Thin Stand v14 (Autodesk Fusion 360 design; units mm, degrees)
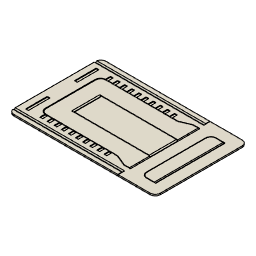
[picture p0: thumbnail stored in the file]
parameter "PhoneThickness" = 7
parameter "d60" = 1.5
parameter "d61" = 2
parameter "d62" = 0.75 (= "0.5 * d60")
sketch "Sketch1" plane through (0, 0, 0) normal (0, 1, 0) x axis (1, 0, 0)
  line L1 (43, 27) -> (-43, 27)
  line L2 (43, -27) -> (43, 27)
  line L3 (-43, -27) -> (43, -27)
  line L4 (-43, 27) -> (-43, -27)
  line L5 (43, -27) -> (-43, 27)
  line L6 (-43, -27) -> (43, 27)
  line L7 (-43, 0) -> (43, 0)
  line L8 (28.2, 20.4) -> (28.2, 0)
  line L9 (36.2, 20.4) -> (28.2, 20.4)
  line L10 (36.2, 0) -> (36.2, 20.4)
  line L11 (28.4, 20.2) -> (28.4, 0)
  line L12 (36, 20.2) -> (28.4, 20.2)
  line L13 (36, 0) -> (36, 20.2)
  line L14 (-24, 8) -> (21, 8)
  line L15 (-24, 0) -> (-24, 8)
  line L16 (21, 8) -> (21, 0)
  line L17 (21.2, 8.2) -> (21.2, 0)
  line L18 (-24.2, 8.2) -> (21, 8.2)
  line L19 (-24.2, 0) -> (-24.2, 8.2)
  line L20 (-33.5, 17.5) -> (-33.5, 0)
  line L21 (11.5, 17.5) -> (-33.5, 17.5)
  line L22 (21, 20.2) -> (21, 8.2)
  line L23 (18, 20.2) -> (21, 20.2)
  line L24 (11.5, 17.5) -> (18, 20.2)
  line L25 (21.2, 20.4) -> (21.2, 8.2)
  line L26 (17.9601, 20.4) -> (21.2, 20.4)
  line L27 (11.4601, 17.7) -> (17.9601, 20.4)
  line L28 (11.4601, 17.7) -> (-33.7, 17.7)
  line L29 (-33.7, 17.7) -> (-33.7, 0)
  line L30 (-33.5, -17.5) -> (-33.5, 0)
  line L31 (11.5, -17.5) -> (-33.5, -17.5)
  line L32 (18, -20.2) -> (21, -20.2)
  line L33 (21, -20.2) -> (21, -8.2)
  line L34 (21.2, -20.4) -> (21.2, -8.2)
  line L35 (21, -8) -> (21, 0)
  line L36 (21.2, -8.2) -> (21.2, 0)
  line L37 (-24, -8) -> (21, -8)
  line L38 (-24.2, -8.2) -> (21, -8.2)
  line L39 (-24.2, 0) -> (-24.2, -8.2)
  line L40 (-24, 0) -> (-24, -8)
  line L41 (28.2, -20.4) -> (28.2, 0)
  line L42 (28.4, -20.2) -> (28.4, 0)
  line L43 (17.9601, -20.4) -> (21.2, -20.4)
  line L44 (11.5, -17.5) -> (18, -20.2)
  line L45 (11.4601, -17.7) -> (17.9601, -20.4)
  line L46 (11.4601, -17.7) -> (-33.7, -17.7)
  line L47 (-33.7, -17.7) -> (-33.7, 0)
  line L48 (36.2, -20.4) -> (28.2, -20.4)
  line L49 (36, -20.2) -> (28.4, -20.2)
  line L50 (36, 0) -> (36, -20.2)
  line L51 (36.2, 0) -> (36.2, -20.4)
  line L52 (43, 24) -> (-43, 24)
  line L53 (43, 23.8) -> (-43, 23.8)
  line L54 (21.2, 27) -> (21.2, 24)
  line L55 (21, 27) -> (21, 24)
  line L56 (43, -23.8) -> (-43, -23.8)
  line L57 (43, -24) -> (-43, -24)
  line L58 (21, -27) -> (21, -24)
  line L59 (21.2, -27) -> (21.2, -24)
  line L60 (21.2, 23.8) -> (21.2, 24)
  line L61 (21.2, -23.8) -> (21.2, -24)
  line L62 (-33.9, 17.9) -> (-33.9, 0)
  line L63 (11.4202, 17.9) -> (-33.9, 17.9)
  line L64 (11.4202, 17.9) -> (17.9202, 20.6)
  line L65 (17.9202, 20.6) -> (21.4, 20.6)
  line L66 (21.4, 20.6) -> (21.4, 7.8)
  line L67 (-23.8, 7.8) -> (21.4, 7.8)
  line L68 (-23.8, 0) -> (-23.8, 7.8)
  line L69 (-33.9, 17.7) -> (-33.7, 17.7)
  line L70 (-33.9, -17.7) -> (-33.7, -17.7)
  line L71 (-33.9, -17.9) -> (-33.9, 0)
  line L72 (-23.323, 10.3151) -> (21, 10.3151)
  point P6 (0, 0)
  point P1 (0, 0)
  point P7 (43, 0)
  point P8 (-43, 0)
  point P9 (28.2, 0)
  point P12 (36.2, 0)
  point P19 (-24, 0)
  point P20 (21, 0)
  point P25 (-33.5, 0)
  point P30 (21.2, 8.2)
  point P36 (21.2, 8.2)
  point P21 (21.2, 0)
  point P24 (-24.2, 0)
  point P53 (28.2, 0)
  point P10 (28.2, 20.4)
  point P54 (28.2, -20.4)
  point P11 (36.2, 20.4)
  point P61 (36.2, -20.4)
  point P64 (36.2, 0)
  point P13 (28.4, 0)
  point P55 (28.4, 0)
  point P14 (28.4, 20.2)
  point P56 (28.4, -20.2)
  point P15 (36, 20.2)
  point P62 (36, -20.2)
  point P16 (36, 0)
  point P63 (36, 0)
  point P17 (21, 8)
  point P46 (21, -8)
  point P18 (-24, 8)
  point P49 (-24, -8)
  point P52 (-24, 0)
  point P45 (21, 0)
  point P47 (21.2, 0)
  point P22 (21, 8.2)
  point P42 (21, -8.2)
  point P23 (-24.2, 8.2)
  point P50 (-24.2, -8.2)
  point P51 (-24.2, 0)
  point P37 (-33.5, 0)
  point P26 (-33.5, 17.5)
  point P38 (-33.5, -17.5)
  point P27 (11.5, 17.5)
  point P39 (11.5, -17.5)
  point P28 (21, 20.2)
  point P40 (21, -20.2)
  point P29 (18, 20.2)
  point P41 (18, -20.2)
  point P43 (21.2, -8.2)
  point P31 (21.2, 20.4)
  point P44 (21.2, -20.4)
  point P32 (17.9601, 20.4)
  point P57 (17.9601, -20.4)
  point P33 (11.4601, 17.7)
  point P58 (11.4601, -17.7)
  point P34 (-33.7, 17.7)
  point P59 (-33.7, -17.7)
  point P35 (-33.7, 0)
  point P60 (-33.7, 0)
  point P48 (21.2, -8.2)
  point P65 (-43, 24)
  point P66 (43, 24)
  point P69 (21.2, 24)
  point P70 (21.2, 27)
  point P75 (-43, -24)
  point P76 (43, -24)
  point P67 (-43, 23.8)
  point P73 (-43, -23.8)
  point P68 (43, 23.8)
  point P74 (43, -23.8)
  point P79 (21.2, -24)
  point P80 (21.2, -27)
  point P71 (21, 24)
  point P77 (21, -24)
  point P72 (21, 27)
  point P78 (21, -27)
  point P81 (21.2, 23.8)
  point P82 (21.2, -24)
  point P83 (21.2, -23.8)
  point P92 (-33.9, 17.7)
  point P93 (-33.7, -17.7)
  point P84 (-33.9, 0)
  point P95 (-33.9, 0)
  point P85 (-33.9, 17.9)
  point P96 (-33.9, -17.9)
  point P94 (-33.9, -17.7)
  point P97 (21, 10.3151)
  point P3 (43, 27)
  point P4 (43, -27)
  point P2 (-43, 27)
  horizontal L1
  perpendicular L1 L2
  parallel L1 L3
  parallel L2 L4
  coincident L5 P6
  coincident L6 P6
  coincident P1 P6
  midpoint L2 P7
  midpoint L4 P8
  coincident L7 P9
  perpendicular L7 L8
  perpendicular L8 L9
  coincident L7 P12
  perpendicular L7 L10
  horizontal L14
  vertical L15
  vertical L16
  coincident L7 P19
  coincident L7 P20
  coincident L7 P25
  perpendicular L7 L20
  perpendicular L20 L21
  perpendicular L18 L22
  perpendicular L22 L23
  parallel L16 L17
  parallel L14 L18
  parallel L15 L19
  coincident P30 P36
  coincident L7 P21
  coincident L7 P24
  symmetric L7 P9 P53
  symmetric L7 P10 P54
  symmetric L7 P11 P61
  symmetric L7 P12 P64
  symmetric L7 P13 P55
  symmetric L7 P14 P56
  symmetric L7 P15 P62
  symmetric L7 P16 P63
  symmetric L7 P17 P46
  symmetric L7 P18 P49
  symmetric L7 P19 P52
  symmetric L7 P20 P45
  symmetric L7 P21 P47
  symmetric L7 P22 P42
  symmetric L7 P23 P50
  symmetric L7 P24 P51
  symmetric L7 P25 P37
  symmetric L7 P26 P38
  symmetric L7 P27 P39
  symmetric L7 P28 P40
  symmetric L7 P29 P41
  symmetric L7 P30 P43
  symmetric L7 P31 P44
  symmetric L7 P32 P57
  symmetric L7 P33 P58
  symmetric L7 P34 P59
  symmetric L7 P35 P60
  symmetric L7 P36 P48
  coincident L4 P65
  coincident L2 P66
  perpendicular L2 L52
  coincident L52 P69
  coincident L1 P70
  perpendicular L1 L54
  symmetric L7 P65 P75
  symmetric L7 P66 P76
  symmetric L7 P67 P73
  symmetric L7 P68 P74
  symmetric L7 P69 P79
  symmetric L7 P70 P80
  symmetric L7 P71 P77
  symmetric L7 P72 P78
  coincident L53 P81
  perpendicular L53 L60
  symmetric L7 P69 P82
  symmetric L7 P81 P83
  coincident L62 P92
  perpendicular L62 L69
  symmetric L7 P34 P93
  symmetric L7 P84 P95
  symmetric L7 P85 P96
  symmetric L7 P92 P94
  coincident L22 P97
  perpendicular L19 L72
  dimension "d1" distance P3 P4 = 54
  dimension "d2" distance P2 P3 = 86
  dimension "d3" distance P10 P11 = 8
  dimension "d4" distance P9 P10 = 20.4
  dimension "d6" = 0.2
  dimension "d7" distance P17 P18 = 45
  dimension "d8" distance L2 L16 = 22
  dimension "d9" distance P17 P20 = 8
  dimension "d11" distance P26 P27 = 45
  dimension "d12" distance P22 P28 = 12
  dimension "d13" distance P28 P29 = 3
  dimension "d14" distance P25 P26 = 17.5
  dimension "d15" distance L15 L20 = 9.5
  dimension "d16" = 0.2
  dimension "d17" distance L14 L18 = 0.2
  dimension "d18" distance L20 L22 = 54.5
  dimension "d19" distance L15 L19 = 0.2
  dimension "d22" distance L8 L17 = 7 (= "PhoneThickness")
  dimension "d49" = 0.2
  dimension "d50" distance L1 L52 = 3
  dimension "d51" = -0.2
  dimension "d52" distance L8 L54 = 7 (= "PhoneThickness")
  dimension "d55" = -0.4
extrude "Extrude1" new body sketch "Sketch1" profile of L1 L2 L3 L4 L8 L9 L10 L11 L13 L12 L14 L15 L16 L17 L18 L19 L20 L21 L22 L23 L24 L27 L25 L26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 along normal blind 0.8
sketch "Sketch2" plane through (0, 0, 0) normal (0, 1, 0) x axis (1, 0, 0)
  line L1 (28.4, -20.2) -> (28.4, 20.2)
  line L2 (36, -20.2) -> (28.4, -20.2)
  line L3 (36, 20.2) -> (36, -20.2)
  line L4 (28.4, 20.2) -> (36, 20.2)
  line L5 (-43, -23.8) -> (-43, 23.8)
  line L6 (43, -27) -> (21.2, -27)
  line L7 (43, 27) -> (43, -27)
  line L8 (21.2, 27) -> (43, 27)
  line L9 (28.2, 20.4) -> (28.2, -20.4)
  line L10 (36.2, 20.4) -> (28.2, 20.4)
  line L11 (36.2, -20.4) -> (36.2, 20.4)
  line L12 (28.2, -20.4) -> (36.2, -20.4)
  line L13 (11.4601, 17.7) -> (-33.9, 17.7)
  line L14 (17.9601, 20.4) -> (11.4601, 17.7)
  line L15 (21.2, 20.4) -> (17.9601, 20.4)
  line L16 (21.2, -20.4) -> (21.2, 20.4)
  line L17 (17.9601, -20.4) -> (21.2, -20.4)
  line L18 (11.4601, -17.7) -> (17.9601, -20.4)
  line L19 (-33.9, -17.7) -> (11.4601, -17.7)
  line L20 (21, 20.2) -> (21, 8.2)
  line L21 (-24.2, -8.2) -> (21, -8.2)
  line L22 (-24.2, 8.2) -> (-24.2, -8.2)
  line L23 (21, 8.2) -> (-24.2, 8.2)
  line L24 (21, 20.2) -> (21, 8.2)
  line L25 (18, 20.2) -> (21, 20.2)
  line L26 (11.5, 17.5) -> (18, 20.2)
  line L27 (-33.5, 17.5) -> (11.5, 17.5)
  line L28 (-33.5, -17.5) -> (-33.5, 17.5)
  line L29 (11.5, -17.5) -> (-33.5, -17.5)
  line L30 (18, -20.2) -> (11.5, -17.5)
  line L31 (21, -20.2) -> (18, -20.2)
  line L32 (21, -8.2) -> (21, -20.2)
  line L33 (21, 8) -> (21, -8)
  line L34 (-24, 8) -> (21, 8)
  line L35 (-24, -8) -> (-24, 8)
  line L36 (21, -8) -> (-24, -8)
  line L37 (36.2, 20.2) -> (36, 20.2)
  line L38 (36.2, -20.2) -> (36, -20.2)
  line L39 (21.2, -8) -> (21, -8)
  line L40 (21.2, 8) -> (21, 8)
  line L41 (-24.2, 8) -> (-24, 8)
  line L42 (-24.2, -8) -> (-24, -8)
  line L43 (21.2, 23.8) -> (21.2, 27)
  line L44 (-43, 23.8) -> (21.2, 23.8)
  line L45 (21.2, -23.8) -> (-43, -23.8)
  line L46 (21.2, -27) -> (21.2, -23.8)
  line L47 (21, -24) -> (-43, -24)
  line L48 (21, -27) -> (21, -24)
  line L49 (-43, -27) -> (21, -27)
  line L50 (21, 27) -> (-43, 27)
  line L51 (21, 24) -> (21, 27)
  line L52 (-43, 24) -> (21, 24)
  line L53 (21, -23.8) -> (21, -24)
  line L54 (-43, -24) -> (-43, -23.8)
  line L55 (-43, 23.8) -> (-43, 24)
  line L56 (-43, -24) -> (-43, -27)
  line L57 (-43, 27) -> (-43, 24)
  line L58 (21, 23.8) -> (21, 24)
  line L59 (-33.9, 17.7) -> (-33.9, -17.7)
  point P5 (36, 20.2)
  point P44 (36, 20.2)
  point P45 (36.2, 20.2)
  point P4 (36, -20.2)
  point P46 (36, -20.2)
  point P47 (36.2, -20.2)
  point P40 (21, -8)
  point P48 (21, -8)
  point P49 (21.2, -8)
  point P41 (21, 8)
  point P50 (21, 8)
  point P51 (21.2, 8)
  point P42 (-24, 8)
  point P52 (-24, 8)
  point P53 (-24.2, 8)
  point P43 (-24, -8)
  point P54 (-24, -8)
  point P55 (-24.2, -8)
  point P60 (21, -24)
  point P66 (21, -24)
  point P67 (21, -23.8)
  point P8 (-43, -23.8)
  point P68 (-43, -23.8)
  point P58 (-43, -24)
  point P69 (-43, -24)
  point P63 (-43, 24)
  point P70 (-43, 24)
  point P7 (-43, 23.8)
  point P71 (-43, 23.8)
  point P65 (21, 24)
  point P72 (21, 24)
  point P73 (21, 23.8)
  coincident P5 P44
  coincident L11 P45
  perpendicular L11 L37
  coincident P4 P46
  coincident L11 P47
  perpendicular L11 L38
  coincident P40 P48
  coincident L16 P49
  perpendicular L16 L39
  coincident P41 P50
  coincident L16 P51
  perpendicular L16 L40
  coincident P42 P52
  coincident L22 P53
  perpendicular L22 L41
  coincident P43 P54
  coincident L22 P55
  perpendicular L22 L42
  coincident P60 P66
  coincident L45 P67
  perpendicular L45 L53
  coincident P8 P68
  coincident P58 P69
  coincident P63 P70
  coincident P7 P71
  coincident P65 P72
  coincident L44 P73
  perpendicular L44 L58
extrude "Extrude2" add sketch "Sketch2" profile of L3 L11 L16 L22 L33 L35 L37 L38 L39 L40 L41 L42 L44 L45 L47 L52 L53 L54 L55 L58 along normal blind 0.2
chamfer "Chamfer1" distance 0.6
fillet "Fillet2" radius 3
sketch "Sketch3" plane through (0, 0.8, 0) normal (0, 1, 0) x axis (-1, 0, 0)
  line L1 (30.9, 17.7) -> (-10.8618, 17.7)
  line L2 (-10.8618, -17.7) -> (30.9, -17.7)
  line L3 (-17.9601, -20.4) -> (-12.0126, -17.9295)
  line L4 (-21.8, -20.4) -> (-17.9601, -20.4)
  line L5 (-21.8, 20.4) -> (-21.8, -20.4)
  line L6 (-17.9601, 20.4) -> (-21.8, 20.4)
  line L7 (-12.0126, 17.9295) -> (-17.9601, 20.4)
  line L8 (-31.2, 20.4) -> (-36.2, 20.4)
  line L9 (-28.2, -17.4) -> (-28.2, 17.4)
  line L10 (-36.2, -20.4) -> (-31.2, -20.4)
  line L11 (43, 23.2) -> (43, -23.2)
  line L12 (-43, 27) -> (-21.2, 27)
  line L13 (-43, -27) -> (-43, 27)
  line L14 (-21.2, -27) -> (-43, -27)
  line L15 (-7.8618, -17.7) -> (-10.8618, -17.7)
  line L16 (-7.8618, -20.7) -> (-7.8618, -17.7)
  line L17 (-6.6618, -20.7) -> (-7.8618, -20.7)
  line L18 (-6.6618, -17.7) -> (-6.6618, -20.7)
  line L19 (-6.6618, -8) -> (-6.6618, -17.7)
  line L20 (-7.8618, -8) -> (-6.6618, -8)
  line L21 (-7.8618, -17.7) -> (-7.8618, -8)
  line L22 (23.4, -8) -> (-20.4, -8)
  line L23 (-2.48, -17.7) -> (-2.48, -20.7)
  line L24 (-2.48, -8) -> (-2.48, -17.7)
  line L25 (-3.68, -17.7) -> (-3.68, -8)
  line L26 (-3.68, -20.7) -> (-3.68, -17.7)
  line L27 (-2.48, -20.7) -> (-3.68, -20.7)
  line L28 (-3.68, -8) -> (-2.48, -8)
  line L29 (-3.68, -17.7) -> (-6.68, -17.7)
  line L30 (1.7018, -17.7) -> (1.7018, -20.7)
  line L31 (1.7018, -8) -> (1.7018, -17.7)
  line L32 (0.5018, -17.7) -> (0.5018, -8)
  line L33 (0.5018, -20.7) -> (0.5018, -17.7)
  line L34 (1.7018, -20.7) -> (0.5018, -20.7)
  line L35 (0.5018, -8) -> (1.7018, -8)
  line L36 (0.5018, -17.7) -> (-2.4982, -17.7)
  line L37 (5.8836, -17.7) -> (5.8836, -20.7)
  line L38 (5.8836, -8) -> (5.8836, -17.7)
  line L39 (4.6836, -17.7) -> (4.6836, -8)
  line L40 (4.6836, -20.7) -> (4.6836, -17.7)
  line L41 (5.8836, -20.7) -> (4.6836, -20.7)
  line L42 (4.6836, -8) -> (5.8836, -8)
  line L43 (4.6836, -17.7) -> (1.6836, -17.7)
  line L44 (10.0655, -17.7) -> (10.0655, -20.7)
  line L45 (10.0655, -8) -> (10.0655, -17.7)
  line L46 (8.8655, -17.7) -> (8.8655, -8)
  line L47 (8.8655, -20.7) -> (8.8655, -17.7)
  line L48 (10.0655, -20.7) -> (8.8655, -20.7)
  line L49 (8.8655, -8) -> (10.0655, -8)
  line L50 (8.8655, -17.7) -> (5.8655, -17.7)
  line L51 (14.2473, -17.7) -> (14.2473, -20.7)
  line L52 (14.2473, -8) -> (14.2473, -17.7)
  line L53 (13.0473, -17.7) -> (13.0473, -8)
  line L54 (13.0473, -20.7) -> (13.0473, -17.7)
  line L55 (14.2473, -20.7) -> (13.0473, -20.7)
  line L56 (13.0473, -8) -> (14.2473, -8)
  line L57 (13.0473, -17.7) -> (10.0473, -17.7)
  line L58 (18.4291, -17.7) -> (18.4291, -20.7)
  line L59 (18.4291, -8) -> (18.4291, -17.7)
  line L60 (17.2291, -17.7) -> (17.2291, -8)
  line L61 (17.2291, -20.7) -> (17.2291, -17.7)
  line L62 (18.4291, -20.7) -> (17.2291, -20.7)
  line L63 (17.2291, -8) -> (18.4291, -8)
  line L64 (17.2291, -17.7) -> (14.2291, -17.7)
  line L65 (22.6109, -17.7) -> (22.6109, -20.7)
  line L66 (22.6109, -8) -> (22.6109, -17.7)
  line L67 (21.4109, -17.7) -> (21.4109, -8)
  line L68 (21.4109, -20.7) -> (21.4109, -17.7)
  line L69 (22.6109, -20.7) -> (21.4109, -20.7)
  line L70 (21.4109, -8) -> (22.6109, -8)
  line L71 (21.4109, -17.7) -> (18.4109, -17.7)
  line L72 (26.7927, -17.7) -> (26.7927, -20.7)
  line L73 (26.7927, -8) -> (26.7927, -17.7)
  line L74 (25.5927, -17.7) -> (25.5927, -8)
  line L75 (25.5927, -20.7) -> (25.5927, -17.7)
  line L76 (26.7927, -20.7) -> (25.5927, -20.7)
  line L77 (25.5927, -8) -> (26.7927, -8)
  line L78 (25.5927, -17.7) -> (22.5927, -17.7)
  line L79 (30.9745, -17.7) -> (30.9745, -20.7)
  line L80 (30.9745, -8) -> (30.9745, -17.7)
  line L81 (29.7745, -17.7) -> (29.7745, -8)
  line L82 (29.7745, -20.7) -> (29.7745, -17.7)
  line L83 (30.9745, -20.7) -> (29.7745, -20.7)
  line L84 (29.7745, -8) -> (30.9745, -8)
  line L85 (29.7745, -17.7) -> (26.7745, -17.7)
  line L86 (35.1564, -17.7) -> (35.1564, -20.7)
  line L87 (35.1564, -8) -> (35.1564, -17.7)
  line L88 (33.9564, -17.7) -> (33.9564, -8)
  line L89 (33.9564, -20.7) -> (33.9564, -17.7)
  line L90 (35.1564, -20.7) -> (33.9564, -20.7)
  line L91 (33.9564, -8) -> (35.1564, -8)
  line L92 (33.9564, -17.7) -> (30.9564, -17.7)
  line L93 (39.3382, -17.7) -> (39.3382, -20.7)
  line L94 (39.3382, -8) -> (39.3382, -17.7)
  line L95 (38.1382, -17.7) -> (38.1382, -8)
  line L96 (38.1382, -20.7) -> (38.1382, -17.7)
  line L97 (39.3382, -20.7) -> (38.1382, -20.7)
  line L98 (38.1382, -8) -> (39.3382, -8)
  line L99 (38.1382, -17.7) -> (35.1382, -17.7)
  line L100 (10, 0) -> (0, 0)
  line L101 (38.1382, 8) -> (39.3382, 8)
  line L102 (21.4109, 20.7) -> (21.4109, 17.7)
  line L103 (25.5927, 17.7) -> (25.5927, 8)
  line L104 (29.7745, 8) -> (30.9745, 8)
  line L105 (17.2291, 17.7) -> (17.2291, 8)
  line L106 (1.7018, 20.7) -> (0.5018, 20.7)
  line L107 (0.5018, 20.7) -> (0.5018, 17.7)
  line L108 (-7.8618, 17.7) -> (-7.8618, 8)
  line L109 (22.6109, 17.7) -> (22.6109, 20.7)
  line L110 (17.2291, 17.7) -> (14.2291, 17.7)
  line L111 (25.5927, 20.7) -> (25.5927, 17.7)
  line L112 (-3.68, 17.7) -> (-6.68, 17.7)
  line L113 (33.9564, 20.7) -> (33.9564, 17.7)
  line L114 (-7.8618, 8) -> (-6.6618, 8)
  line L115 (35.1564, 20.7) -> (33.9564, 20.7)
  line L116 (13.0473, 8) -> (14.2473, 8)
  line L117 (17.2291, 20.7) -> (17.2291, 17.7)
  line L118 (22.6109, 20.7) -> (21.4109, 20.7)
  line L119 (25.5927, 17.7) -> (22.5927, 17.7)
  line L120 (39.3382, 8) -> (39.3382, 17.7)
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  point P7 (-10.8618, -17.7)
  point P30 (-10.8618, -17.7)
  point P34 (-6.6618, -17.7)
  point P36 (-7.8618, -8)
  point P1 (0, 0)
  point P116 (0, 0)
  point P6 (33.9, -14.7)
  point P155 (33.9, 14.7)
  point P142 (-10.8618, 17.7)
  point P8 (-12.0126, -17.9295)
  point P132 (-12.0126, 17.9295)
  point P10 (-17.9601, -20.4)
  point P207 (-17.9601, 20.4)
  point P11 (-21.8, -20.4)
  point P197 (-21.8, 20.4)
  point P22 (-21.2, -27)
  point P124 (-21.2, 27)
  point P23 (43, -23.2)
  point P183 (43, 23.2)
  point P202 (-10.8618, 17.7)
  point P31 (-7.8618, -17.7)
  point P156 (-7.8618, 17.7)
  point P32 (-7.8618, -20.7)
  point P150 (-7.8618, 20.7)
  point P33 (-6.6618, -20.7)
  point P158 (-6.6618, 20.7)
  point P210 (-6.6618, 17.7)
  point P35 (-6.6618, -8)
  point P120 (-6.6618, 8)
  point P187 (-7.8618, 8)
  point P37 (-20.4, -8)
  point P143 (-20.4, 8)
  point P38 (23.4, -8)
  point P118 (23.4, 8)
  point P39 (-2.48, -20.7)
  point P157 (-2.48, 20.7)
  point P40 (-2.48, -17.7)
  point P149 (-2.48, 17.7)
  point P41 (-2.48, -8)
  point P127 (-2.48, 8)
  point P42 (-3.68, -8)
  point P134 (-3.68, 8)
  point P43 (-3.68, -17.7)
  point P172 (-3.68, 17.7)
  point P44 (-3.68, -20.7)
  point P160 (-3.68, 20.7)
  point P45 (-6.68, -17.7)
  point P206 (-6.68, 17.7)
  point P46 (1.7018, -20.7)
  point P171 (1.7018, 20.7)
  point P47 (1.7018, -17.7)
  point P190 (1.7018, 17.7)
  point P48 (1.7018, -8)
  point P137 (1.7018, 8)
  point P49 (0.5018, -8)
  point P119 (0.5018, 8)
  point P50 (0.5018, -17.7)
  point P195 (0.5018, 17.7)
  point P51 (0.5018, -20.7)
  point P213 (0.5018, 20.7)
  point P52 (-2.4982, -17.7)
  point P200 (-2.4982, 17.7)
  point P53 (5.8836, -20.7)
  point P193 (5.8836, 20.7)
  point P54 (5.8836, -17.7)
  point P198 (5.8836, 17.7)
  point P55 (5.8836, -8)
  point P159 (5.8836, 8)
  point P56 (4.6836, -8)
  point P135 (4.6836, 8)
  point P57 (4.6836, -17.7)
  point P162 (4.6836, 17.7)
  point P58 (4.6836, -20.7)
  point P165 (4.6836, 20.7)
  point P59 (1.6836, -17.7)
  point P211 (1.6836, 17.7)
  point P60 (10.0655, -20.7)
  point P170 (10.0655, 20.7)
  point P61 (10.0655, -17.7)
  point P145 (10.0655, 17.7)
  point P62 (10.0655, -8)
  point P126 (10.0655, 8)
  point P63 (8.8655, -8)
  point P136 (8.8655, 8)
  point P64 (8.8655, -17.7)
  point P147 (8.8655, 17.7)
  point P65 (8.8655, -20.7)
  point P141 (8.8655, 20.7)
  point P66 (5.8655, -17.7)
  point P192 (5.8655, 17.7)
  point P67 (14.2473, -20.7)
  point P125 (14.2473, 20.7)
  point P68 (14.2473, -17.7)
  point P179 (14.2473, 17.7)
  point P69 (14.2473, -8)
  point P208 (14.2473, 8)
  point P70 (13.0473, -8)
  point P201 (13.0473, 8)
  point P71 (13.0473, -17.7)
  point P177 (13.0473, 17.7)
  point P72 (13.0473, -20.7)
  point P184 (13.0473, 20.7)
  point P73 (10.0473, -17.7)
  point P196 (10.0473, 17.7)
  point P74 (18.4291, -20.7)
  point P175 (18.4291, 20.7)
  point P75 (18.4291, -17.7)
  point P122 (18.4291, 17.7)
  point P76 (18.4291, -8)
  point P191 (18.4291, 8)
  point P77 (17.2291, -8)
  point P194 (17.2291, 8)
  point P78 (17.2291, -17.7)
  point P138 (17.2291, 17.7)
  point P79 (17.2291, -20.7)
  point P151 (17.2291, 20.7)
  point P80 (14.2291, -17.7)
  point P130 (14.2291, 17.7)
  point P81 (22.6109, -20.7)
  point P169 (22.6109, 20.7)
  point P82 (22.6109, -17.7)
  point P188 (22.6109, 17.7)
  point P83 (22.6109, -8)
  point P204 (22.6109, 8)
  point P84 (21.4109, -8)
  point P163 (21.4109, 8)
  point P85 (21.4109, -17.7)
  point P214 (21.4109, 17.7)
  point P86 (21.4109, -20.7)
  point P209 (21.4109, 20.7)
  point P87 (18.4109, -17.7)
  point P129 (18.4109, 17.7)
  point P88 (26.7927, -20.7)
  point P174 (26.7927, 20.7)
  point P89 (26.7927, -17.7)
  point P176 (26.7927, 17.7)
  point P90 (26.7927, -8)
  point P161 (26.7927, 8)
  point P91 (25.5927, -8)
  point P167 (25.5927, 8)
  point P92 (25.5927, -17.7)
  point P185 (25.5927, 17.7)
  point P93 (25.5927, -20.7)
  point P173 (25.5927, 20.7)
  point P94 (22.5927, -17.7)
  point P144 (22.5927, 17.7)
  point P95 (30.9745, -20.7)
  point P181 (30.9745, 20.7)
  point P96 (30.9745, -17.7)
  point P182 (30.9745, 17.7)
  point P97 (30.9745, -8)
  point P164 (30.9745, 8)
  point P98 (29.7745, -8)
  point P168 (29.7745, 8)
  point P99 (29.7745, -17.7)
  point P178 (29.7745, 17.7)
  point P100 (29.7745, -20.7)
  point P186 (29.7745, 20.7)
  point P101 (26.7745, -17.7)
  point P128 (26.7745, 17.7)
  point P102 (35.1564, -20.7)
  point P123 (35.1564, 20.7)
  point P103 (35.1564, -17.7)
  point P121 (35.1564, 17.7)
  point P104 (35.1564, -8)
  point P203 (35.1564, 8)
  point P105 (33.9564, -8)
  point P189 (33.9564, 8)
  point P106 (33.9564, -17.7)
  point P139 (33.9564, 17.7)
  point P107 (33.9564, -20.7)
  point P148 (33.9564, 20.7)
  point P108 (30.9564, -17.7)
  point P133 (30.9564, 17.7)
  point P109 (39.3382, -20.7)
  point P146 (39.3382, 20.7)
  point P110 (39.3382, -17.7)
  point P153 (39.3382, 17.7)
  point P111 (39.3382, -8)
  point P199 (39.3382, 8)
  point P112 (38.1382, -8)
  point P212 (38.1382, 8)
  point P113 (38.1382, -17.7)
  point P154 (38.1382, 17.7)
  point P114 (38.1382, -20.7)
  point P166 (38.1382, 20.7)
  point P115 (35.1382, -17.7)
  point P205 (35.1382, 17.7)
  coincident P7 P30
  parallel L2 L15
  perpendicular L15 L16
  perpendicular L16 L17
  coincident L2 P34
  perpendicular L2 L18
  perpendicular L2 L19
  perpendicular L19 L20
  perpendicular L15 L21
  coincident P36 L22
  coincident P1 P116
  perpendicular L9 L100
  symmetric P6 L100 P155
  symmetric P7 L100 P142
  symmetric P8 L100 P132
  symmetric P10 L100 P207
  symmetric P11 L100 P197
  symmetric P22 L100 P124
  symmetric P23 L100 P183
  symmetric P30 L100 P202
  symmetric P31 L100 P156
  symmetric P32 L100 P150
  symmetric P33 L100 P158
  symmetric P34 L100 P210
  symmetric P35 L100 P120
  symmetric P36 L100 P187
  symmetric P37 L100 P143
  symmetric P38 L100 P118
  symmetric P39 L100 P157
  symmetric P40 L100 P149
  symmetric P41 L100 P127
  symmetric P42 L100 P134
  symmetric P43 L100 P172
  symmetric P44 L100 P160
  symmetric P45 L100 P206
  symmetric P46 L100 P171
  symmetric P47 L100 P190
  symmetric P48 L100 P137
  symmetric P49 L100 P119
  symmetric P50 L100 P195
  symmetric P51 L100 P213
  symmetric P52 L100 P200
  symmetric P53 L100 P193
  symmetric P54 L100 P198
  symmetric P55 L100 P159
  symmetric P56 L100 P135
  symmetric P57 L100 P162
  symmetric P58 L100 P165
  symmetric P59 L100 P211
  symmetric P60 L100 P170
  symmetric P61 L100 P145
  symmetric P62 L100 P126
  symmetric P63 L100 P136
  symmetric P64 L100 P147
  symmetric P65 L100 P141
  symmetric P66 L100 P192
  symmetric P67 L100 P125
  symmetric P68 L100 P179
  symmetric P69 L100 P208
  symmetric P70 L100 P201
  symmetric P71 L100 P177
  symmetric P72 L100 P184
  symmetric P73 L100 P196
  symmetric P74 L100 P175
  symmetric P75 L100 P122
  symmetric P76 L100 P191
  symmetric P77 L100 P194
  symmetric P78 L100 P138
  symmetric P79 L100 P151
  symmetric P80 L100 P130
  symmetric P81 L100 P169
  symmetric P82 L100 P188
  symmetric P83 L100 P204
  symmetric P84 L100 P163
  symmetric P85 L100 P214
  symmetric P86 L100 P209
  symmetric P87 L100 P129
  symmetric P88 L100 P174
  symmetric P89 L100 P176
  symmetric P90 L100 P161
  symmetric P91 L100 P167
  symmetric P92 L100 P185
  symmetric P93 L100 P173
  symmetric P94 L100 P144
  symmetric P95 L100 P181
  symmetric P96 L100 P182
  symmetric P97 L100 P164
  symmetric P98 L100 P168
  symmetric P99 L100 P178
  symmetric P100 L100 P186
  symmetric P101 L100 P128
  symmetric P102 L100 P123
  symmetric P103 L100 P121
  symmetric P104 L100 P203
  symmetric P105 L100 P189
  symmetric P106 L100 P139
  symmetric P107 L100 P148
  symmetric P108 L100 P133
  symmetric P109 L100 P146
  symmetric P110 L100 P153
  symmetric P111 L100 P199
  symmetric P112 L100 P212
  symmetric P113 L100 P154
  symmetric P114 L100 P166
  symmetric P115 L100 P205
  dimension "d30" distance P30 P31 = 3
  dimension "d31" distance P31 P32 = 3
  dimension "d32" distance P32 P33 = 1.2
  dimension "d35" R-Pattern1-uDistance = 46
  dimension "d36" R-Pattern1-vDistance = 0
extrude "Extrude3" cut sketch "Sketch3" against normal blind 0.4
sketch "Sketch4" plane through (0, 0, 0) normal (0, -1, 0) x axis (1, 0, 0)
  line L1 (17.9601, 20.4) -> (12.0126, 17.9295)
  line L2 (21.2, 20.4) -> (17.9601, 20.4)
  line L3 (21.2, 8) -> (21.2, 20.4)
  line L4 (-24.2, 8) -> (21.2, 8)
  line L5 (-24.2, 8.2) -> (-24.2, 8)
  line L6 (21, 8.2) -> (-24.2, 8.2)
  line L7 (21, 20.2) -> (21, 8.2)
  line L8 (18, 20.2) -> (21, 20.2)
  line L9 (12.0525, 17.7295) -> (18, 20.2)
  line L10 (-30.5, 17.5) -> (10.9017, 17.5)
  line L11 (-33.5, -14.5) -> (-33.5, 14.5)
  line L12 (10.9017, -17.5) -> (-30.5, -17.5)
  line L13 (18, -20.2) -> (12.0525, -17.7295)
  line L14 (21, -20.2) -> (18, -20.2)
  line L15 (21, -8.2) -> (21, -20.2)
  line L16 (-24.2, -8.2) -> (21, -8.2)
  line L17 (-24.2, -8) -> (-24.2, -8.2)
  line L18 (21.2, -8) -> (-24.2, -8)
  line L19 (21.2, -20.4) -> (21.2, -8)
  line L20 (17.9601, -20.4) -> (21.2, -20.4)
  line L21 (12.0126, -17.9295) -> (17.9601, -20.4)
  line L22 (-30.9, -17.7) -> (10.8618, -17.7)
  line L23 (10.8618, 17.7) -> (-30.9, 17.7)
  line L24 (43, -27) -> (21.2, -27)
  line L25 (43, 27) -> (43, -27)
  line L26 (21.2, 27) -> (43, 27)
  line L27 (-43, 24) -> (-43, 27)
  line L28 (36.2, -20.2) -> (31.4, -20.2)
  line L29 (36.2, -20.4) -> (36.2, -20.2)
  line L30 (31.2, -20.4) -> (36.2, -20.4)
  line L31 (28.2, 17.4) -> (28.2, -17.4)
  line L32 (36.2, 20.4) -> (31.2, 20.4)
  line L33 (36.2, 20.2) -> (36.2, 20.4)
  line L34 (31.4, 20.2) -> (36.2, 20.2)
  line L35 (28.4, -17.2) -> (28.4, 17.2)
  line L36 (-33.5, 0) -> (-33.9, 0)
  line L37 (21.2, 14.2) -> (21, 14.2)
  line L38 (21, -14.2) -> (21.2, -14.2)
  line L39 (28.2, 0) -> (28.4, 0)
  line L40 (-33.9, 0.4) -> (-33.5, 0.4)
  line L41 (-33.9, -0.4) -> (-33.9, 0.4)
  line L42 (-33.5, -0.4) -> (-33.9, -0.4)
  line L43 (-33.5, 0.4) -> (-33.5, -0.4)
  line L44 (-33.9, -0.4) -> (-33.5, 0.4)
  line L45 (-33.5, -0.4) -> (-33.9, 0.4)
  line L46 (21, 14.6) -> (21.2, 14.6)
  line L47 (21, 13.8) -> (21, 14.6)
  line L48 (21.2, 13.8) -> (21, 13.8)
  line L49 (21.2, 14.6) -> (21.2, 13.8)
  line L50 (21, 13.8) -> (21.2, 14.6)
  line L51 (21.2, 13.8) -> (21, 14.6)
  line L52 (28.1, 0.4) -> (28.5, 0.4)
  line L53 (28.1, -0.4) -> (28.1, 0.4)
  line L54 (28.5, -0.4) -> (28.1, -0.4)
  line L55 (28.5, 0.4) -> (28.5, -0.4)
  line L56 (28.1, -0.4) -> (28.5, 0.4)
  line L57 (28.5, -0.4) -> (28.1, 0.4)
  line L58 (21, -13.8) -> (21.2, -13.8)
  line L59 (21, -14.6) -> (21, -13.8)
  line L60 (21.2, -14.6) -> (21, -14.6)
  line L61 (21.2, -13.8) -> (21.2, -14.6)
  line L62 (21, -14.6) -> (21.2, -13.8)
  line L63 (21.2, -14.6) -> (21, -13.8)
  line L64 (21.2, 23.8) -> (21.2, 27)
  line L65 (21, 23.8) -> (21.2, 23.8)
  line L66 (21.2, -23.8) -> (21, -23.8)
  line L67 (21.2, -27) -> (21.2, -23.8)
  line L68 (21, 27) -> (21, 24)
  line L69 (21.2, 27) -> (43, 27)
  line L70 (43, -27) -> (21.2, -27)
  line L71 (21, -24) -> (21, -27)
  line L72 (-11, 23.8) -> (-11, 24)
  line L73 (-42.9998, 23.8) -> (21, 23.8)
  line L74 (-42.9998, 24) -> (-42.9998, 23.8)
  line L75 (21, 24) -> (-42.9998, 24)
  line L76 (21, 23.8) -> (21, 24)
  line L77 (-42.9998, 24) -> (21, 23.8)
  line L78 (21, 24) -> (-42.9998, 23.8)
  line L79 (-11, -23.8) -> (-11, -24)
  line L80 (-43, -24) -> (21, -24)
  line L81 (-43, -23.8) -> (-43, -24)
  line L82 (21, -23.8) -> (-43, -23.8)
  line L83 (21, -24) -> (21, -23.8)
  line L84 (-43, -23.8) -> (21, -24)
  line L85 (21, -23.8) -> (-43, -24)
  line L86 (-43, 24) -> (-43, 27)
  line L87 (-43, 24) -> (-43, 27)
  line L88 (21, 24) -> (21, 23.8)
  line L89 (21, 27) -> (21, 24)
  line L90 (-43, 27) -> (21, 27)
  line L91 (-43, 23.8) -> (-43, 24)
  line L92 (-43, -23.8) -> (-43, 23.8)
  line L93 (-43, -24) -> (-43, -23.8)
  line L94 (-43, -27) -> (-43, -24)
  line L95 (21, -27) -> (-43, -27)
  line L96 (21, -24) -> (21, -27)
  line L97 (21, -23.8) -> (21, -24)
  line L98 (36.2, -20.2) -> (31.4, -20.2)
  line L99 (36.2, -20.4) -> (36.2, -20.2)
  line L100 (31.2, -20.4) -> (36.2, -20.4)
  line L101 (28.2, 17.4) -> (28.2, -17.4)
  line L102 (36.2, 20.4) -> (31.2, 20.4)
  line L103 (36.2, 20.2) -> (36.2, 20.4)
  line L104 (31.4, 20.2) -> (36.2, 20.2)
  line L105 (28.4, -17.2) -> (28.4, 17.2)
  line L106 (21.2, -27) -> (21.2, -23.8)
  line L107 (43, -27) -> (21.2, -27)
  line L108 (43, 27) -> (43, -27)
  line L109 (21.2, 23.8) -> (21.2, 27)
  line L110 (21, 23.8) -> (21.2, 23.8)
  line L111 (21, 24) -> (21, 23.8)
  line L112 (-43, 27) -> (21, 27)
  line L113 (-43, 23.8) -> (-43, 24)
  line L114 (-43, -23.8) -> (-43, 23.8)
  line L115 (-43, -24) -> (-43, -23.8)
  line L116 (-43, -27) -> (-43, -24)
  line L117 (21, -27) -> (-43, -27)
  line L118 (21, -24) -> (21, -27)
  line L119 (21, -23.8) -> (21, -24)
  line L120 (21.2, -23.8) -> (21, -23.8)
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  point P63 (-33.5, 0)
  point P64 (21, 14.2)
  point P65 (21.2, 14.2)
  point P66 (21.2, -14.2)
  point P67 (21, -14.2)
  point P68 (28.4, 0)
  point P69 (28.2, 0)
  point P70 (-33.5, 0.4)
  point P74 (-33.7, 0)
  point P79 (21.1, 14.2)
  point P84 (28.3, 0)
  point P89 (21.1, -14.2)
  point P101 (-11, 23.8)
  point P102 (21, 23.8)
  point P106 (-11, 23.9)
  point P94 (21, 24)
  point P105 (21, 24)
  point P108 (-11, -23.8)
  point P99 (21, -24)
  point P109 (21, -24)
  point P113 (-11, -23.9)
  point P77 (21, 13.8)
  point P78 (21.2, 13.8)
  point P76 (21, 14.6)
  point P81 (28.1, 0.4)
  point P82 (28.1, -0.4)
  point P87 (21, -14.6)
  point P88 (21.2, -14.6)
  point P86 (21, -13.8)
  midpoint L11 P63
  midpoint L7 P64
  midpoint L3 P65
  midpoint L19 P66
  midpoint L15 P67
  midpoint L35 P68
  midpoint L31 P69
  horizontal L40
  perpendicular L40 L41
  parallel L40 L42
  parallel L41 L43
  coincident L11 P70
  coincident L44 P74
  coincident L45 P74
  midpoint L36 P74
  horizontal L46
  perpendicular L46 L47
  parallel L46 L48
  parallel L47 L49
  coincident L50 P79
  coincident L51 P79
  midpoint L37 P79
  horizontal L52
  perpendicular L52 L53
  parallel L52 L54
  parallel L53 L55
  coincident L56 P84
  coincident L57 P84
  midpoint L39 P84
  horizontal L58
  perpendicular L58 L59
  parallel L58 L60
  parallel L59 L61
  coincident L62 P89
  coincident L63 P89
  midpoint L38 P89
  coincident L65 P101
  perpendicular L65 L72
  horizontal L73
  perpendicular L73 L74
  parallel L73 L75
  parallel L74 L76
  coincident L65 P102
  coincident L77 P106
  coincident L78 P106
  midpoint L72 P106
  coincident P94 P105
  coincident L66 P108
  perpendicular L66 L79
  horizontal L80
  perpendicular L80 L81
  parallel L80 L82
  parallel L81 L83
  coincident P99 P109
  coincident L84 P113
  coincident L85 P113
  midpoint L79 P113
  dimension "d39" distance P77 P78 = 0.2
  dimension "d40" distance P76 P77 = 0.8
  dimension "d41" distance P81 P82 = 0.8
  dimension "d42" distance P87 P88 = 0.2
  dimension "d43" distance P86 P87 = 0.8
  dimension "d46" distance L40 L42 = 0.8
extrude "Extrude4" add sketch "Sketch4" profile of L3 L7 L11 L15 L19 L31 L35 L36 L37 L38 L39 L40 L41 L42 L43 L46 L47 L48 L49 L52 L53 L54 L55 L58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 against normal blind 0.25
chamfer "Chamfer2" distance 0.4
fillet "Fillet3" radius 3
chamfer "Chamfer4" distance 0.4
